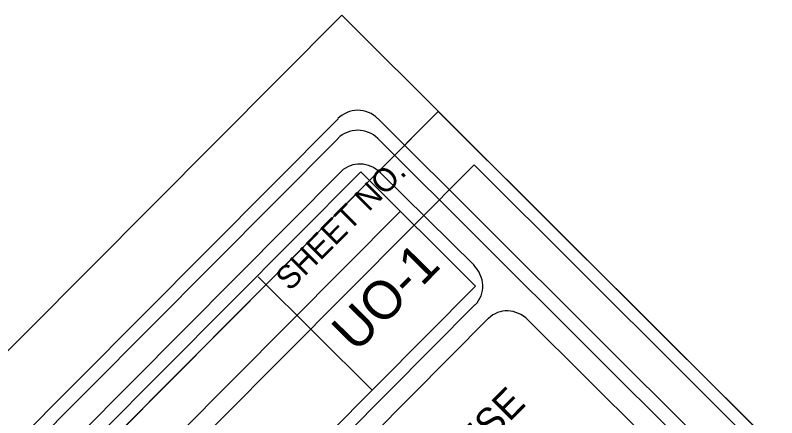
# Model space of a CAD drawing. Extents: x 1484850 to 1495577, y 495475 to 506245.
# Drawn here: x 1488133 to 1488945, y 501057 to 501486 of the extents above; entities that cross this region are included whole.
import ezdxf

# ---------------------------------------------------------------- set-up
doc = ezdxf.new("R2010")
doc.units = 0
for name, color, linetype in [('Cell Prop Down Guy _B', 7, 'Continuous'), ('Exist Utilities Power UG Cable SUE LOS C', 7, 'Continuous'), ('P Pole (Pow Co) CELL', 7, 'Continuous'), ('Prop Guy Wire', 7, 'Continuous'), ('Prop UG Pow Cables', 7, 'Continuous')]:
    doc.layers.add(name, color=color, linetype=linetype)

msp = doc.modelspace()

# ---------------------------------------------------------------- linework, layer by layer
at = {"layer": 'Cell Prop Down Guy _B'}
msp.add_line((1485019.38, 497803.89), (1488584.25, 501383.61), dxfattribs=at)
msp.add_lwpolyline([(1485019.38, 497803.89), (1488584.25, 501383.61), (1490922.52, 499055.04), (1487357.65, 495475.32)], close=True, dxfattribs=at)
at = {"layer": 'Exist Utilities Power UG Cable SUE LOS C'}
for p, q in [((1488480.65, 501319.74), (1487939.89, 500776.25)), ((1487941.57, 500757.11), (1488501.6, 501319.26)), ((1488501.6, 501319.26), (1488623.93, 501197.22)), ((1488622.4, 501219.81), (1488522.57, 501318.16)), ((1487983.69, 500714.74), (1488543.74, 501276.86)), ((1488392.08, 501207.31), (1488513.7, 501086.36)), ((1488063.91, 500635.07), (1488623.93, 501197.22)), ((1488082.63, 500633.83), (1488623.37, 501177.35)), ((1488637.93, 501163.12), (1488097.17, 500619.62)), ((1488845.3, 500997.49), (1488679.86, 501161.53))]:
    msp.add_line(p, q, dxfattribs=at)
for centre, major_axis, ratio, start_param, end_param in [((1488502.53, 501297.95), (-21.78, 21.69), 0.926296, 4.712758, 6.283554), ((1488601.85, 501199.09), (21.78, -21.69), 0.941469, 0.000472, 1.571267), ((1488659.81, 501141.32), (-21.78, 21.69), 0.926296, 4.712758, 6.283554)]:
    msp.add_ellipse(centre, major_axis=major_axis, ratio=ratio, start_param=start_param, end_param=end_param, dxfattribs=at)
at = {"layer": 'P Pole (Pow Co) CELL'}
msp.add_lwpolyline([(1488481.29, 501486.15), (1484916.42, 497906.42), (1487254.69, 495577.85), (1490819.56, 499157.58)], close=True, dxfattribs=at)
at = {"layer": 'Prop Guy Wire'}
msp.add_lwpolyline([(1487337.48, 495550.45), (1490865.3, 499092.97), (1488622.45, 501326.52), (1485094.62, 497784)], close=True, dxfattribs=at)
at = {"layer": 'Prop UG Pow Cables'}
for points in [[(1488477.3, 501375.85), (1485344.2, 498229.75)], [(1490709.17, 499195.53), (1488519.7, 501375.92)], [(1488477.32, 501354.61), (1485471.34, 498336.11)], [(1490294.73, 499587.09), (1488519.72, 501354.73)]]:
    msp.add_lwpolyline(points, dxfattribs=at)
for centre in [(1488498.42, 501354.79), (1488498.46, 501333.58)]:
    msp.add_arc(centre, 30, 45.11911, 135.11911, dxfattribs=at)

# ---------------------------------------------------------------- texts
at = {"layer": 'Exist Utilities Power UG Cable SUE LOS C'}
for s, height, p in [('SHEET NO.', 24.745, (1488425.87, 501191.24)), ('UO-1', 40.837, (1488496.24, 501125.37)), ('ALL UTILITY WORK SHOWN ON THESE ', 30, (1488150.67, 500540.02))]:
    msp.add_text(s, height=height, rotation=45.14762, dxfattribs=at).set_placement(p)

doc.saveas('drawing.dxf')
